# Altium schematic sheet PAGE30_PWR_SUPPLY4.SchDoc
size 431 x 304 mm; SheetNumber: 28; SheetTotal: 28
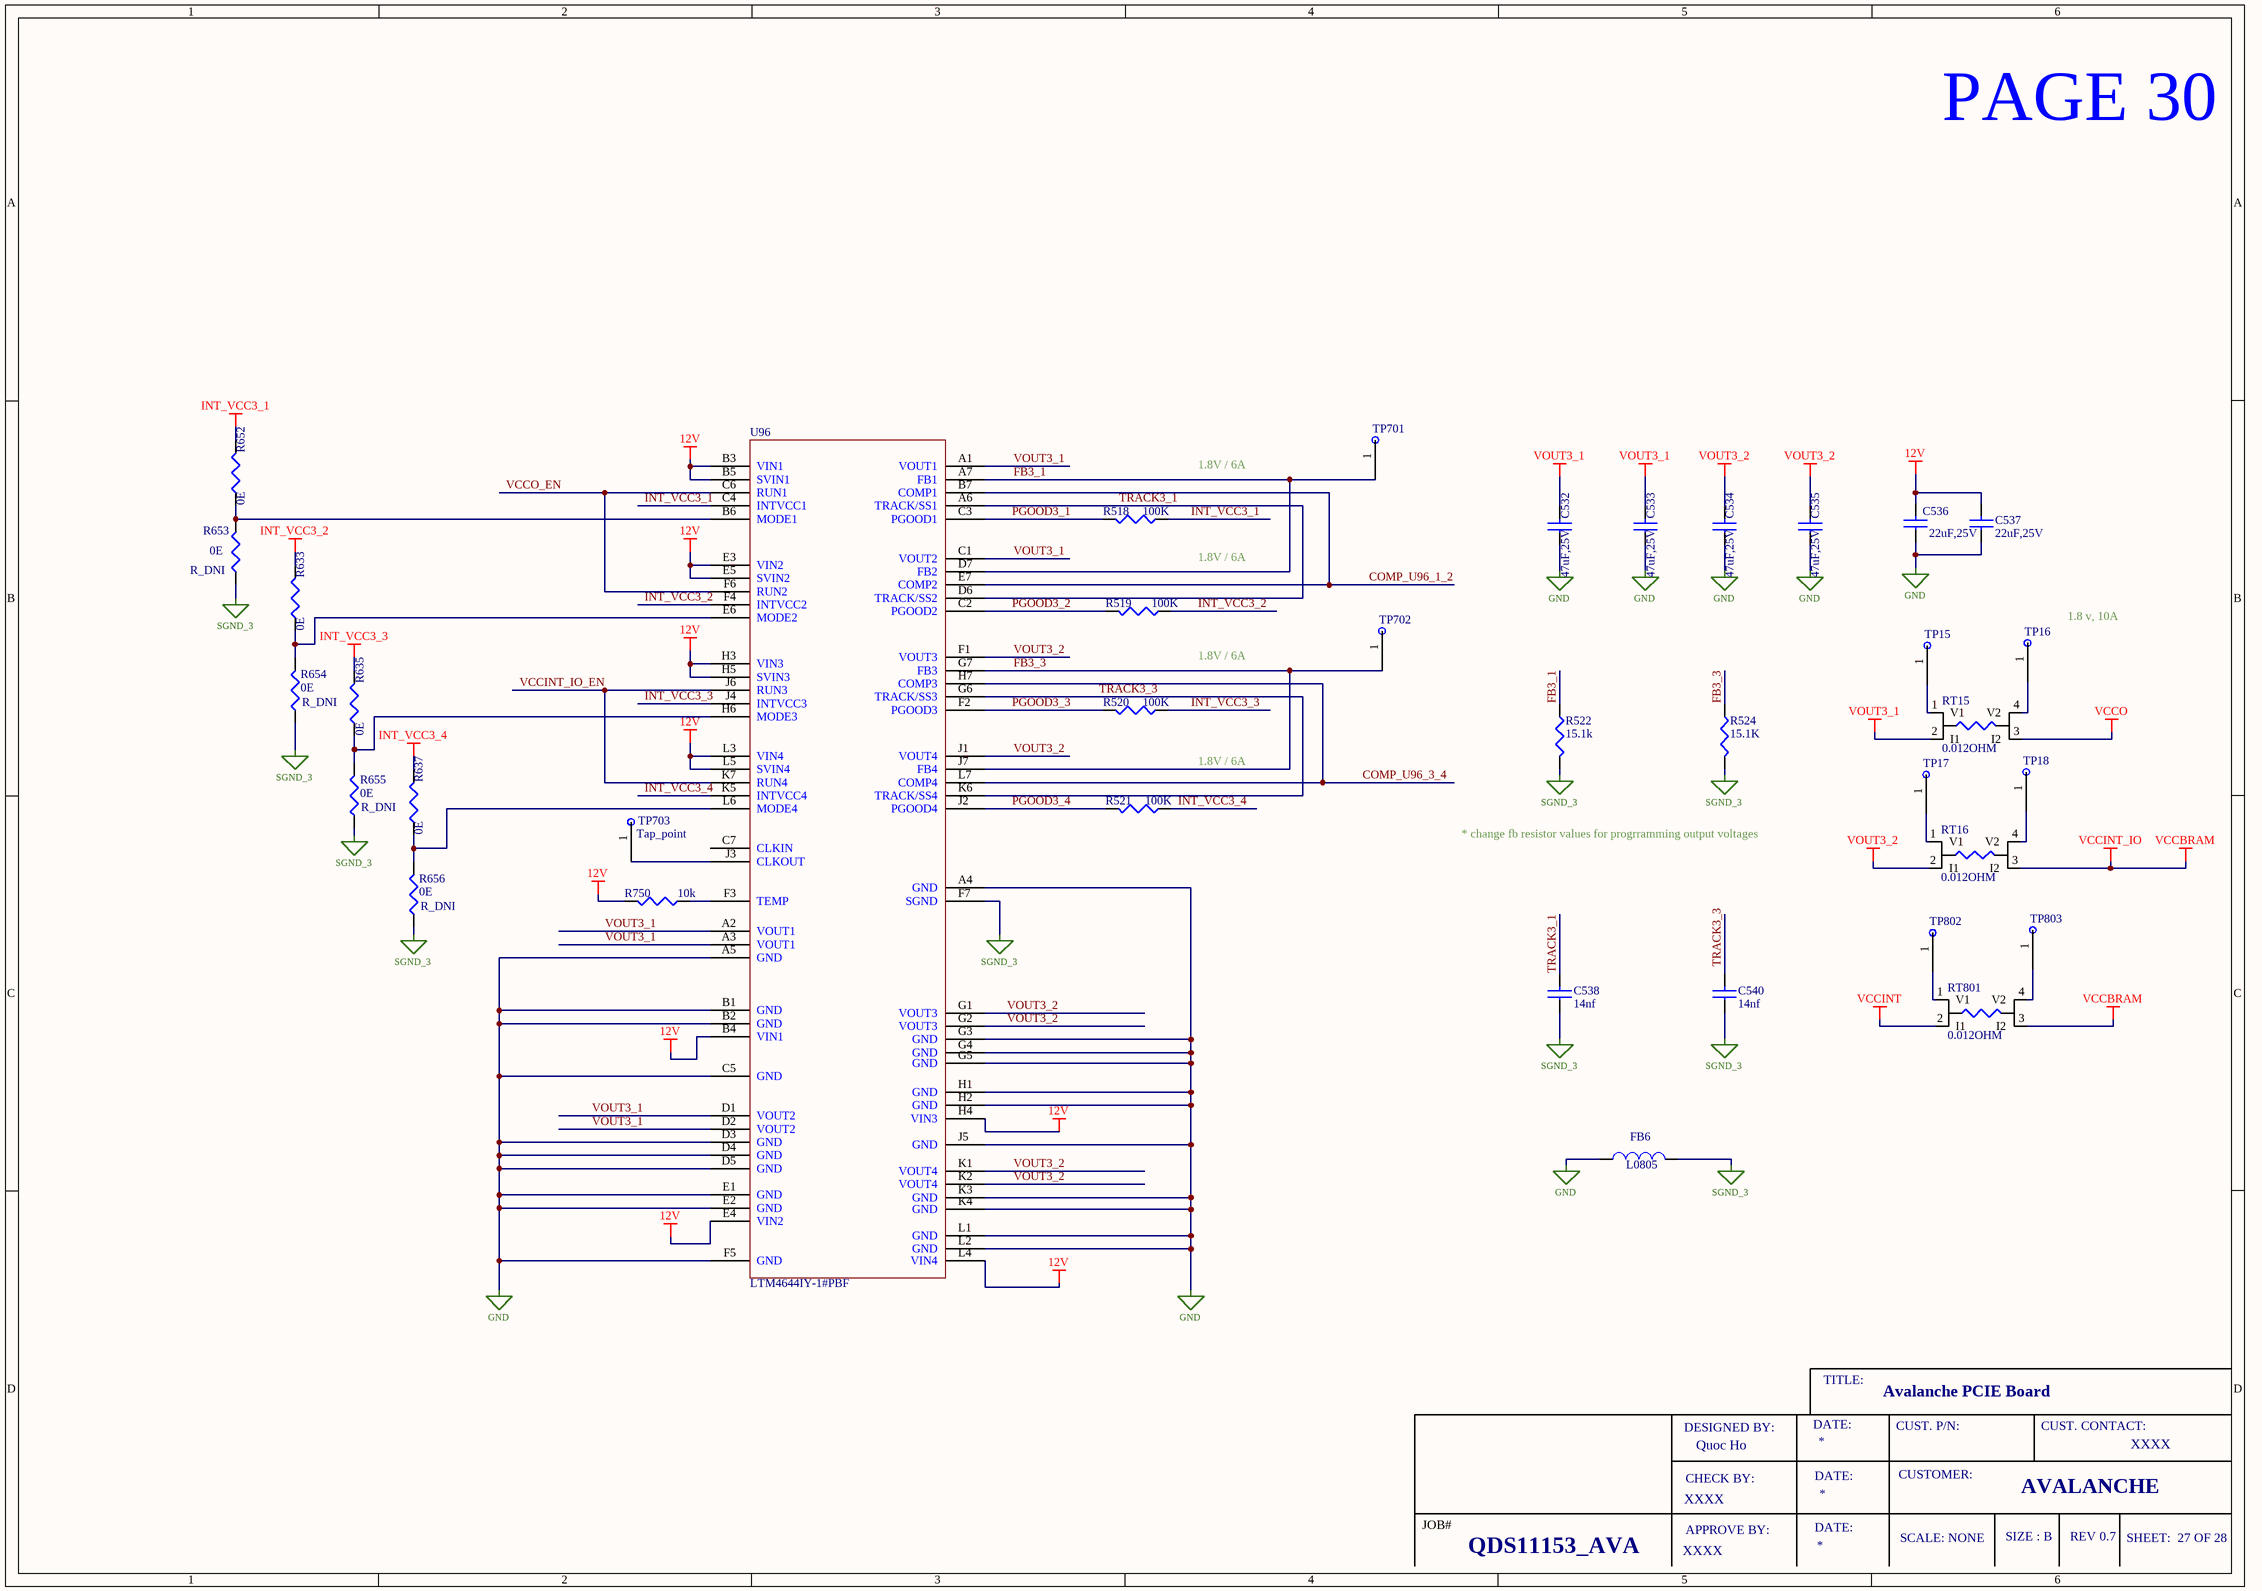
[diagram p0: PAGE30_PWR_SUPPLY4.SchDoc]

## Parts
C532  47uF,25V  [CN_1210]
C533  47uF,25V  [CN_1210]
C534  47uF,25V  [CN_1210]
C535  47uF,25V  [CN_1210]
C536  22uF,25V  [CN_1210]
C537  22uF,25V  [CN_1210]
C538  14nf  [CN_0402]
C540  14nf  [CN_0402]
FB6  L0805  [L0805]
R518  100K  [RN_0402]
R519  100K  [RN_0402]
R520  100K  [RN_0402]
R521  100K  [RN_0402]
R522  15.1k  [RN_0402]
R524  15.1K  [RN_0402]
R633  0E  [RN_0402]
R635  0E  [RN_0402]
R637  0E  [RN_0402]
R652  0E  [RN_0402]
R653  0E  [RN_0402]
R654  0E  [RN_0402]
R655  0E  [RN_0402]
R656  0E  [RN_0402]
R750  10k  [RN_0402]
RT15  0.012OHM  [LVK12]
RT16  0.012OHM  [LVK12]
RT801  0.012OHM  [LVK12]
TP15  Tap_point  [MINI_TESTPOINT_SMD]  (value not drawn)
TP16  Tap_point  [MINI_TESTPOINT_SMD]  (value not drawn)
TP17  Tap_point  [MINI_TESTPOINT_SMD]  (value not drawn)
TP18  Tap_point  [MINI_TESTPOINT_SMD]  (value not drawn)
TP701  Tap_point  [MINI_TESTPOINT]  (value not drawn)
TP702  Tap_point  [MINI_TESTPOINT]  (value not drawn)
TP703  Tap_point  [MINI_TESTPOINT]
TP802  Tap_point  [MINI_TESTPOINT_SMD]  (value not drawn)
TP803  Tap_point  [MINI_TESTPOINT_SMD]  (value not drawn)
U96  LTM4644IY-1#PBF  [BGA77_15X9X1P5_ANALOG]

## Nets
12V: C536.2 C537.2 R750.2 U96.B3(VIN1) U96.B4(VIN1) U96.B5(SVIN1) U96.E3(VIN2) U96.E4(VIN2) U96.E5(SVIN2) U96.H3(VIN3) U96.H4(VIN3) U96.H5(SVIN3) U96.L3(VIN4) U96.L4(VIN4) U96.L5(SVIN4)
GND: C532.1 C533.1 C534.1 C535.1 C536.1 C537.1 FB6.1 U96.A4(GND) U96.A5(GND) U96.B1(GND) U96.B2(GND) U96.C5(GND) U96.D3(GND) U96.D4(GND) U96.D5(GND) U96.E1(GND) U96.E2(GND) U96.F5(GND) U96.G3(GND) U96.G4(GND) U96.G5(GND) U96.H1(GND) U96.H2(GND) U96.J5(GND) U96.K3(GND) U96.K4(GND) U96.L1(GND) U96.L2(GND)
INT_VCC3_1: R518.1 R652.2 U96.C4(INTVCC1)
INT_VCC3_2: R519.1 R633.2 U96.F4(INTVCC2)
INT_VCC3_3: R520.1 R635.2 U96.J4(INTVCC3)
INT_VCC3_4: R521.1 R637.2 U96.K5(INTVCC4)
SGND_3: C538.1 C540.1 FB6.2 R522.2 R524.2 R653.1 R654.1 R655.1 R656.1 U96.F7(SGND)
VCCBRAM: RT16.3(I2) RT801.3(I2)  [also labelled VCCINT_IO]
VCCINT: RT801.2(I1)
VCCO: RT15.3(I2)
VOUT3_1: C532.2 C533.2 RT15.2(I1) U96.A1(VOUT1) U96.A2(VOUT1) U96.A3(VOUT1) U96.C1(VOUT2) U96.D1(VOUT2) U96.D2(VOUT2)
VOUT3_2: C534.2 C535.2 RT16.2(I1) U96.F1(VOUT3) U96.G1(VOUT3) U96.G2(VOUT3) U96.J1(VOUT4) U96.K1(VOUT4) U96.K2(VOUT4)
COMP_U96_1_2: U96.B7(COMP1) U96.E7(COMP2)
COMP_U96_3_4: U96.H7(COMP3) U96.L7(COMP4)
FB3_1: R522.1 TP701.1 U96.A7(FB1) U96.D7(FB2)
FB3_3: R524.1 TP702.1 U96.G7(FB3) U96.J7(FB4)
PGOOD3_1: R518.2 U96.C3(PGOOD1)
PGOOD3_2: R519.2 U96.C2(PGOOD2)
PGOOD3_3: R520.2 U96.F2(PGOOD3)
PGOOD3_4: R521.2 U96.J2(PGOOD4)
TRACK3_1: C538.2 U96.A6(TRACK/SS1) U96.D6(TRACK/SS2)
TRACK3_3: C540.2 U96.G6(TRACK/SS3) U96.K6(TRACK/SS4)
VCCINT_IO_EN: U96.J6(RUN3) U96.K7(RUN4)
VCCO_EN: U96.C6(RUN1) U96.F6(RUN2)
NetR633_1: R633.1 R654.2 U96.E6(MODE2)
NetR635_1: R635.1 R655.2 U96.H6(MODE3)
NetR637_1: R637.1 R656.2 U96.L6(MODE4)
NetR652_1: R652.1 R653.2 U96.B6(MODE1)
NetR750_1: R750.1 U96.F3(TEMP)
NetRT15_1: RT15.1(V1) TP15.1
NetRT15_4: RT15.4(V2) TP16.1
NetRT16_1: RT16.1(V1) TP17.1
NetRT16_4: RT16.4(V2) TP18.1
NetRT801_1: RT801.1(V1) TP802.1
NetRT801_4: RT801.4(V2) TP803.1
NetTP703_1: TP703.1 U96.J3(CLKOUT)

Not connected (* = marked no-connect by the designer): U96 C7(CLKIN)

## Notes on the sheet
- PAGE 30
- 1.8V / 6A
- (near TP16) 1.8 v, 10A
- * change fb resistor values for progrramming output voltages
- TITLE:
- Avalanche PCIE Board
- DESIGNED BY:
- CHECK BY:
- Quoc Ho
- DATE:
- CUST. P/N:
- CUSTOMER:
- CUST. CONTACT:
- XXXX
- JOB#
- APPROVE BY:
- SCALE: NONE
- SIZE : B
- AVALANCHE
- REV 0.7
- SHEET:  27 OF 28
- QDS11153_AVA

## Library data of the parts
C532-C535 = CAP: CAP CER 47UF 25V X5R 1210; Manufacturer Part Number: KGM32LR51E476MU; Manufacturer: KYOCERA AVX
C536 C537 = CAP: CAP CER 22UF 25V X5R 1210; Manufacturer Part Number: CL32A226KAJNNNE; Manufacturer: Samsung Electro-Mechanics
C538 C540 = CAP: CAP CER 0402 15NF 50V X7R 5%; Manufacturer Part Number: C0402C153J5RECTU; Manufacturer: KEMET
FB6 = INDUCTOR: FERRITE BEAD 110 OHM 0805 1LN; Manufacturer Part Number: BLM21SP111SZ1D; Manufacturer: Murata Electronics
R518-R521 = RES: RES 100K OHM 1% 1/16W 0402; Manufacturer Part Number: RC0402FR-07100KL; Manufacturer: YAGEO
R522 = RES: RES SMD 15K OHM 0.1% 1/16W 0402; Manufacturer: YAGEO; Manufacturer Part Number: RT0402BRD0715KL
R524 = RES: RES SMD 15K OHM 0.1% 1/16W 0402; Manufacturer Part Number: RT0402BRD0715KL; Manufacturer: YAGEO
R633 R635 R637 R652 = RES: RES 0 OHM JUMPER 1/16W 0402; Manufacturer Part Number: RC0402JR-070RL; Manufacturer: YAGEO
R653-R656 = RES: RES 0 OHM JUMPER 1/16W 0402; Manufacturer Part Number: RC0402FR-070RL_DNI; Manufacturer: YAGEO
R750 = RES: RES 10K OHM 1% 1/16W 0402; Manufacturer: YAGEO; Manufacturer Part Number: RC0402FR-0710KL
RT15 RT16 RT801 = LVK24: RES 0.012OHM 1% 1/2W 1206; Manufacturer: OHMITE
TP15-TP18 TP701-TP703 TP802 TP803 = Tap_point: Tap_point 15X25
U96 = LTM4644IY-1#PBF_2908: DC DC CONVERTER 4X0.6-5.5V; Manufacturer: Analog Devices Inc.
